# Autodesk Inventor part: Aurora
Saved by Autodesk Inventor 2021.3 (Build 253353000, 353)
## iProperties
Created: 2022-09
Part Number: Aurora
Material: Generic
Document SubType Name: Modeling
Designer: Administrator
Density: 1 g/cm^3
Appearance: Default
Title: Aurora v4
Author: Administrator
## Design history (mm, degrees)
feature "Body6"
feature "Socket Body" [Body]
feature "Shade Ring" [Body]
feature "Shade Ring +Collar" [Body]
feature "Socket" [Body]
feature "Body1"
feature "Metal Strain Relief" [Body]
feature "Fabric Cord (1)" [Body]
feature "Stem (Threaded)" [Body]
feature "Cap (Threaded)" [Body]
feature "Body1 (1)"
body "Solid1"
body "Solid2"
body "Solid3"
body "Solid4"
body "Solid5"
body "Solid6"
body "Solid7"
body "Solid8"
body "Solid9"
body "Solid10"
body "Solid11"
